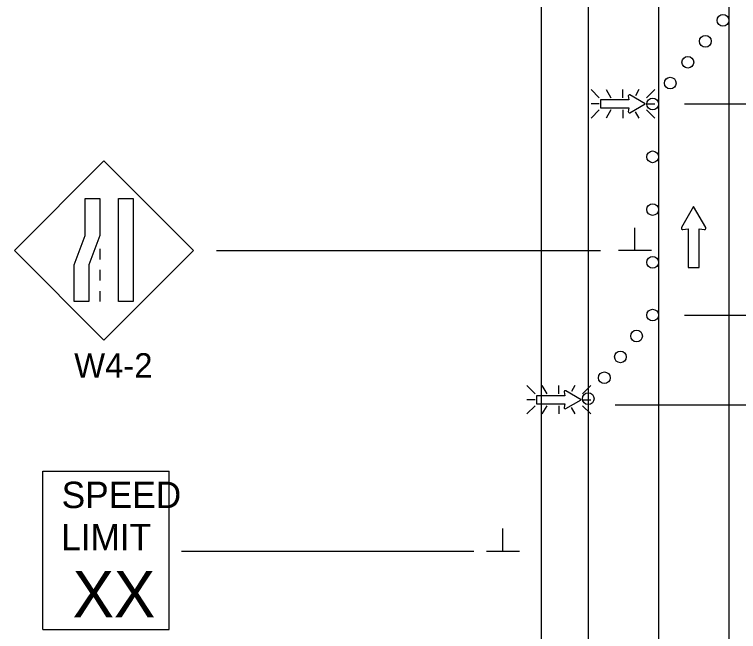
# Model space of a CAD drawing. Extents: x 16504 to 18480, y 5523 to 6928.
# Drawn here: x 16736.8 to 16983.9, y 6455.4 to 6665.9 of the extents above; entities that cross this region are included whole.
import ezdxf

# ---------------------------------------------------------------- set-up
doc = ezdxf.new("R2010")
doc.units = 0
for name, color, linetype in [('ALI_LEGAL_EX', 7, 'Continuous'), ('MT_SCRATCH_LEVEL_E', 7, 'Continuous'), ('PAVT_EDGE_EX', 7, 'Continuous'), ('TRAFFIC_SIGNS_PR', 7, 'Continuous'), ('TYPICAL_TEXT_DIMEN_PR', 7, 'Continuous')]:
    doc.layers.add(name, color=color, linetype=linetype)

msp = doc.modelspace()

# ---------------------------------------------------------------- linework, layer by layer
at = {"layer": 'ALI_LEGAL_EX'}
for p, q in [((16956.63, 6927.83), (16956.63, 6083.69)), ((16980.63, 6927.83), (16980.63, 6083.69))]:
    msp.add_line(p, q, dxfattribs=at)
for points in [[(16956.63, 6627.83), (16956.63, 6602.83)], [(16980.63, 6627.83), (16980.63, 6602.83)], [(16956.63, 6527.83), (16956.63, 6502.83)], [(16980.63, 6527.83), (16980.63, 6502.83)]]:
    msp.add_lwpolyline(points, dxfattribs=at)
at = {"layer": 'MT_SCRATCH_LEVEL_E'}
for p, q in [((16968.6, 6600.4), (16964.49, 6593.16)), ((16972.75, 6593.16), (16968.6, 6600.4)), ((16964.97, 6592.48), (16966.75, 6592.79)), ((16966.75, 6592.79), (16966.75, 6579.54)), ((16970.49, 6579.54), (16970.49, 6592.79)), ((16970.49, 6592.79), (16972.27, 6592.48)), ((16966.75, 6579.54), (16970.49, 6579.54))]:
    msp.add_line(p, q, dxfattribs=at)
for centre, start, end in [((16964.9, 6592.94), 150.4248, 279.9638), ((16972.34, 6592.94), 260.0362, 29.7731)]:
    msp.add_arc(centre, 0.463, start, end, dxfattribs=at)
at = {"layer": 'PAVT_EDGE_EX'}
for p, q in [((16916.63, 6919.19), (16916.63, 6002.83)), ((16932.63, 6919.19), (16932.63, 6002.83))]:
    msp.add_line(p, q, dxfattribs=at)
at = {"layer": 'TRAFFIC_SIGNS_PR'}
for p, q in [((16936.41, 6637.43), (16933.59, 6640.25)), ((16938.71, 6640.25), (16940.33, 6637.43)), ((16944.49, 6637.43), (16944.49, 6640.25)), ((16949.96, 6640.25), (16948.76, 6638.15)), ((16955.4, 6640.24), (16952.58, 6637.43)), ((16936.41, 6635.4), (16933.59, 6635.4)), ((16952.58, 6635.4), (16955.4, 6635.4)), ((16936.41, 6633.36), (16933.59, 6630.54)), ((16940.36, 6633.36), (16938.73, 6630.54)), ((16944.49, 6633.36), (16944.49, 6630.54)), ((16955.4, 6630.55), (16952.58, 6633.36)), ((16948.68, 6632.73), (16949.94, 6630.54)), ((16767.36, 6615.92), (16736.81, 6585.37)), ((16797.9, 6585.37), (16767.36, 6615.92)), ((16736.81, 6585.37), (16767.36, 6554.82)), ((16765.95, 6585.92), (16765.95, 6582.32)), ((16767.36, 6554.82), (16797.9, 6585.37)), ((16765.95, 6578.72), (16765.95, 6575.12)), ((16765.95, 6571.52), (16765.95, 6567.92)), ((16914.54, 6536.48), (16911.72, 6539.3)), ((16916.83, 6539.3), (16918.46, 6536.48)), ((16922.62, 6536.48), (16922.62, 6539.3)), ((16928.09, 6539.3), (16926.88, 6537.2)), ((16933.53, 6539.29), (16930.71, 6536.48)), ((16914.54, 6534.44), (16911.72, 6534.44)), ((16930.71, 6534.44), (16933.53, 6534.44)), ((16914.54, 6532.41), (16911.72, 6529.59)), ((16918.49, 6532.41), (16916.86, 6529.59)), ((16922.62, 6532.41), (16922.62, 6529.59)), ((16926.8, 6531.78), (16928.06, 6529.59)), ((16933.53, 6529.59), (16930.71, 6532.41)), ((16746.43, 6510.02), (16789.63, 6510.02)), ((16746.43, 6456.02), (16746.43, 6510.02)), ((16789.63, 6456.02), (16789.63, 6510.02)), ((16746.43, 6456.02), (16789.63, 6456.02))]:
    msp.add_line(p, q, dxfattribs=at)
for points in [[(16946.32, 6638.08), (16946.55, 6636.78), (16936.83, 6636.78), (16936.83, 6634.04), (16946.55, 6634.04), (16946.32, 6632.73)], [(16946.82, 6632.38), (16952.13, 6635.4), (16946.82, 6638.44)], [(16924.45, 6537.12), (16924.68, 6535.83), (16914.96, 6535.83), (16914.96, 6533.09), (16924.68, 6533.09), (16924.45, 6531.78)], [(16924.95, 6531.43), (16930.26, 6534.44), (16924.95, 6537.48)]]:
    msp.add_lwpolyline(points, dxfattribs=at)
for points in [[(16765.95, 6603.07), (16765.95, 6590.49), (16762.19, 6580.5), (16762.19, 6567.92), (16757.14, 6567.92), (16757.14, 6580.5), (16760.9, 6590.49), (16760.9, 6603.07)], [(16777.36, 6603.07), (16777.36, 6567.92), (16772.3, 6567.92), (16772.3, 6603.07)]]:
    msp.add_lwpolyline(points, close=True, dxfattribs=at)
for centre in [(16978.63, 6663.89), (16972.63, 6656.75), (16966.63, 6649.61), (16960.63, 6642.47), (16954.63, 6635.33), (16954.63, 6617.32), (16954.63, 6599.32), (16954.63, 6581.32), (16954.63, 6563.32), (16949.14, 6556.19), (16943.64, 6549.07), (16938.14, 6541.94), (16932.64, 6534.81)]:
    msp.add_circle(centre, 2, dxfattribs=at)
for centre, start, end in [((16946.66, 6638.14), 61.4833, 189.9593), ((16946.66, 6632.68), 170.7308, 298.8916), ((16924.78, 6537.18), 61.4833, 189.9593), ((16924.78, 6531.73), 170.7308, 298.8916)]:
    msp.add_arc(centre, 0.341, start, end, dxfattribs=at)
at = {"layer": 'TYPICAL_TEXT_DIMEN_PR'}
for p, q in [((17096.68, 6635.32), (16965.53, 6635.32)), ((16948.56, 6585.32), (16948.56, 6593.11)), ((16805.8, 6585.32), (16936.83, 6585.32)), ((16954.19, 6585.32), (16942.94, 6585.32)), ((16965.53, 6563.32), (17096.68, 6563.32)), ((16941.8, 6532.76), (17069.63, 6532.76)), ((16903.51, 6482.76), (16903.51, 6490.55)), ((16793.86, 6482.76), (16893.63, 6482.76)), ((16897.88, 6482.76), (16909.13, 6482.76))]:
    msp.add_line(p, q, dxfattribs=at)

# ---------------------------------------------------------------- texts
at = {"layer": 'TRAFFIC_SIGNS_PR'}
for s, height, p in [('W4-2', 8.37, (16757.18, 6541.95)), ('SPEED', 9, (16752.91, 6497.48)), ('LIMIT', 9, (16752.73, 6483.08)), ('XX', 15.785, (16756.68, 6460.24))]:
    msp.add_text(s, height=height, dxfattribs=at).set_placement(p)

doc.saveas('drawing.dxf')
